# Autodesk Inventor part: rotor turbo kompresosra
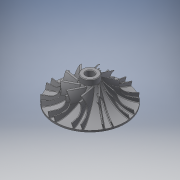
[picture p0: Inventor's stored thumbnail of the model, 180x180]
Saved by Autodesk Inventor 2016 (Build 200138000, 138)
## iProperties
Created: 2015-03
Part Number: rotor turbo kompresosra
Material: Generic
Document SubType Name: Modeling
Designer: Uglješa
Density: 1 g/cm^3
Appearance: Default
Mass: 181.591 g
Surface Area: 557.796 cm^2
Volume: 181.591 cm^3
Author: Uglješa
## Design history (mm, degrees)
sketch "Sketch1"
  geometry: L1 (0, 78.056)-(0, -95.023); L2 (0, 50)-(15, 50); L3 (15, 50)-(15, 40); L4 (69, 3)-(69, 0); L5 (0, 50)-(0, -5); L6 (0, -5)-(15, -5); L7 (69, 0)-(35, 0); A1 r 42.5 centre (35, -42.5) between (35, 0) and (15, -5); A2 r 57.905 centre (69, 60.905) between (15, 40) and (69, 3); 1 further point
  constraints: 14 end point, 5 point on line, 4 point on circle, 2 centre point, 2 perpendicular, 1 parallel, 1 tangent, 1 vertical
  dimensions: "d0" = 10 distance of L2.end L3.end; "d3" = 30 diameter of L3 L1; "d4" = 50 distance from line of point (0, 0) L2; "d6" = 3 distance of L4.start L4.end; "d7" = 138 diameter of L4 L1; "d8" = 55 distance between parallel lines of L6 L2; "d9" = 70 diameter of L7.end L1; "d10" = 30 diameter of L6.end L1
revolve "Revolution1" sketch "Sketch1" stored, may be unused: angle "d11" = 90 deg
workplane "Work Plane2"
  workplane "Work Plane1"
workplane "Work Plane3"
sketch "Sketch3"
  geometry: L1 (69, 0)-(65.623, 21.322); L2 (65.623, 21.322)-(55.822, 40.557); L3 (55.822, 40.557)-(40.557, 55.822); L4 (40.557, 55.822)-(21.322, 65.623); L5 (21.322, 65.623)-(0, 69); L6 (-21.322, 65.623)-(-40.557, 55.822); L7 (-40.557, 55.822)-(-55.822, 40.557); L8 (-55.822, 40.557)-(-65.623, 21.322); L9 (-65.623, 21.322)-(-69, 0); L10 (-69, 0)-(-65.623, -21.322); L11 (-65.623, -21.322)-(-55.822, -40.557); L12 (-55.822, -40.557)-(-40.557, -55.822); L13 (-40.557, -55.822)-(-21.322, -65.623); L14 (-21.322, -65.623)-(0, -69); L15 (0, -69)-(21.322, -65.623); L16 (21.322, -65.623)-(40.557, -55.822); L17 (40.557, -55.822)-(55.822, -40.557); L18 (55.822, -40.557)-(65.623, -21.322); L19 (65.623, -21.322)-(69, 0); L20 (-21.322, 65.623)-(0, 69); 2 further points
  constraints: 40 end point, 11 perpendicular, 2 parallel, 1 vertical alignment, 22 other
  dimensions: "d23" = 360 deg dimension on point (0, 0) L5.end (derived)
sketch "Sketch6"
  geometry: L1 (0, 0)-(0, 90.593) reference; L2 (-15, 0)-(32.767, 60.723); L3 (0, 0)-(-134.085, 0); C1 r 37.5 at (0, 0); A1 r 15 centre (0, 0) between (5.293, 14.035) and (-15, 0) reference; 1 further point
  constraints: 6 end point, 2 point on circle, 2 vertical, 1 centre point, 1 coincident, 1 perpendicular, 2 other
  dimensions: "d31" = 75 diameter of C1; "d208" = 38.19 deg angle of L2 L1; "d216" = 0 distance from line of L2.start L3
workplane "Work Plane7"
sketch "Sketch12"
  geometry: L1 (-6.768, 23)-(0, 3); A1 r 25 centre (-30.449, 14.986) between (-6.768, 23) and (-26.355, 39.649); 1 further point
  constraints: 2 end point, 2 point on circle, 1 centre point, 1 tangent
  dimensions: "d264" = 25 radius of A1; "d266" = 20 vertical distance of L1.start L1.end
sketch "Sketch13"
  geometry: L1 (15, 0)-(15, 40); L2 (-69, 0)-(69, 0) reference; 1 further point
  constraints: 2 end point, 1 point on line, 1 vertical
  dimensions: "d93" = 40 distance of L1.start L1.end
feature "LoftSrf21" sketch "Sketch12", "Sketch13" dims "d108" = 0, "d109" = 90 deg, "d110" = 0, "d111" = 90 deg
pattern_circular "Circular Pattern3" dims angle "d113" = 360 deg
sketch "Sketch14"
  geometry: L1 (-0.509, -25.606)-(-0.509, -41.551) reference; L2 (-0.509, 76.402)-(91.556, 76.402); L3 (91.556, 76.402)-(91.556, -5); L4 (91.556, -5)-(66.991, -5); L5 (66.991, -5)-(66.991, 20); L6 (-15, -5)-(15, -5) reference; L7 (-0.509, 76.402)-(0, 58.172); L8 (0, 58.172)-(15, 58.591); L9 (15, 58.591)-(15.519, 40); L10 (15.519, 40)-(38.706, 40); A1 r 30 centre (66.991, 50) between (38.706, 40) and (66.991, 20); 2 further points
  constraints: 18 end point, 4 parallel, 4 point on line, 3 perpendicular, 2 point on circle, 2 vertical, 1 centre point, 1 midpoint
  dimensions: "d162" = 135 diameter of L5 L1; "d164" = 30 radius of A1; "d165" = 25 distance of L4.end L5.end
revolve "Revolution5" sketch "Sketch14" stored, may be unused: angle "d166" = 90 deg
sketch "Sketch15"
  geometry: C1 r 15 at (0, 0) reference; C2 r 7.5 at (0, 0)
  constraints: 1 centre point, 1 coincident
  dimensions: "d167" = 15 diameter of C2
extrude "Extrusion5" cut sketch "Sketch15" stored distance "d169" = 10; taper "d170" = 0 deg
pattern_circular "Circular Pattern4" dims angle "d181" = 360 deg
thicken "Thicken23" dims "d183" = 1.25, "d184" = 1.25
thicken "Thicken24" dims "d185" = 1.25, "d186" = 1.25
thicken "Thicken25" dims "d187" = 1.25, "d188" = 1.25
thicken "Thicken26" dims "d189" = 1.25, "d190" = 1.25
thicken "Thicken27" dims "d191" = 1.25, "d192" = 1.25
thicken "Thicken28" dims "d193" = 1.25, "d194" = 1.25
thicken "Thicken29" dims "d195" = 1.25, "d196" = 1.25
thicken "Thicken30" dims "d197" = 1.25, "d198" = 1.25
thicken "Thicken31" dims "d199" = 1.25, "d200" = 1.25
thicken "Thicken32" dims "d201" = 1.25, "d202" = 1.25
sketch "Sketch18"
  geometry: L1 (-15, 3)-(-21.167, 19.943); L2 (-109.617, 30)-(174.702, 30) reference; L3 (0, -26.248)-(0, -9.678) reference; A1 r 18 centre (-38.081, 13.787) between (-21.167, 19.943) and (-30.262, 30); 1 further point
  constraints: 4 end point, 2 point on circle, 1 centre point, 1 perpendicular, 1 point on line, 1 tangent, 1 vertical
  dimensions: "d221" = 18 radius of A1; "d272" = 16.94343 vertical distance of L1.start L1.end; "d273" = 15 horizontal distance of point (0, 0) L1.start; "d274" = 3 vertical distance of point (0, 0) L1.start; "d275" = 20 deg angle of L3 L1
sketch "Sketch19"
  geometry: L1 (15, 30.003)-(15, 2.916); L2 (0, 57.914)-(0, 52.147) reference; 1 further point
  constraints: 4 end point, 2 vertical, 1 parallel
  dimensions: "d224" = 30 diameter of L1 L2
feature "LoftSrf60" sketch "Sketch18", "Sketch19" dims "d226" = 0, "d227" = 90 deg, "d228" = 0, "d229" = 90 deg
pattern_circular "Circular Pattern5" dims angle "d231" = 360 deg
thicken "Thicken33" dims "d233" = 1.25, "d234" = 1.25
thicken "Thicken34" dims "d235" = 1.25, "d236" = 1.25
thicken "Thicken35" dims "d237" = 1.25, "d238" = 1.25
thicken "Thicken36" dims "d239" = 1.25, "d240" = 1.25
thicken "Thicken37" dims "d241" = 1.25, "d242" = 1.25
thicken "Thicken38" dims "d243" = 1.25, "d244" = 1.25
thicken "Thicken39" dims "d245" = 1.25, "d246" = 1.25
thicken "Thicken40" dims "d247" = 1.25, "d248" = 1.25
thicken "Thicken41" dims "d249" = 1.25, "d250" = 1.25
thicken "Thicken42" dims "d251" = 1.25, "d252" = 1.25
sketch "Sketch16"
  geometry: L1 (0, 0)-(0, 0) reference; L2 (41.735, 62.973)-(111.445, 62.973); L3 (111.445, 62.973)-(124.053, 27.311); L4 (66, 12)-(66, -14.252); L5 (66, -14.252)-(124.053, -14.252); L6 (124.053, -14.252)-(124.053, 27.311); L7 (39, 27)-(39, 52.349); L8 (39, 52.349)-(39, 62.973); L9 (39, 62.973)-(41.735, 62.973); L10 (54, 12)-(66, 12); L11 (0, 120.354)-(0, -39.329) reference; A1 r 15 centre (54, 27) between (39, 27) and (54, 12); 1 further point
  constraints: 20 end point, 3 point on circle, 2 parallel, 2 perpendicular, 2 tangent, 2 vertical, 1 centre point, 1 horizontal
  dimensions: "d258" = 15 radius of A1; "d260" = 12 distance from line of L1 L4.start; "d280" = 132 diameter of L4 L11
fillet "Fillet13" dims "d254" = 1
fillet "Fillet15" dims "d256" = 2.5
chamfer "Chamfer1" distance "d261" = 1; stored, may be unused: second distance "d262" = 2, angle "d263" = 45 deg
fillet "Fillet16" dims "d270" = 2.5
revolve "Revolution7" stored, may be unused: angle "d278" = 90 deg
body "Solid1"
body "Srf23"
body "Srf24"
body "Srf25"
body "Srf26"
body "Srf27"
body "Srf28"
body "Srf29"
body "Srf30"
body "Srf31"
body "Srf32"
body "Srf43"
body "Srf44"
body "Srf45"
body "Srf46"
body "Srf47"
body "Srf48"
body "Srf49"
body "Srf50"
body "Srf51"
body "Srf62"
body "Srf63"
body "Srf64"
body "Srf65"
body "Srf66"
body "Srf67"
body "Srf68"
body "Srf69"
body "Srf70"
body "Srf71"
feature "LoftSrf22"
feature "LoftSrf23"
feature "LoftSrf24"
feature "LoftSrf25"
feature "LoftSrf26"
feature "LoftSrf27"
feature "LoftSrf28"
feature "LoftSrf29"
feature "LoftSrf30"
feature "LoftSrf41"
feature "LoftSrf42"
feature "LoftSrf43"
feature "LoftSrf44"
feature "LoftSrf45"
feature "LoftSrf46"
feature "LoftSrf47"
feature "LoftSrf48"
feature "LoftSrf49"
feature "LoftSrf61"
feature "LoftSrf62"
feature "LoftSrf63"
feature "LoftSrf64"
feature "LoftSrf65"
feature "LoftSrf66"
feature "LoftSrf67"
feature "LoftSrf68"
feature "LoftSrf69"
other parameters: "d18" = -3, "d81" = 75
